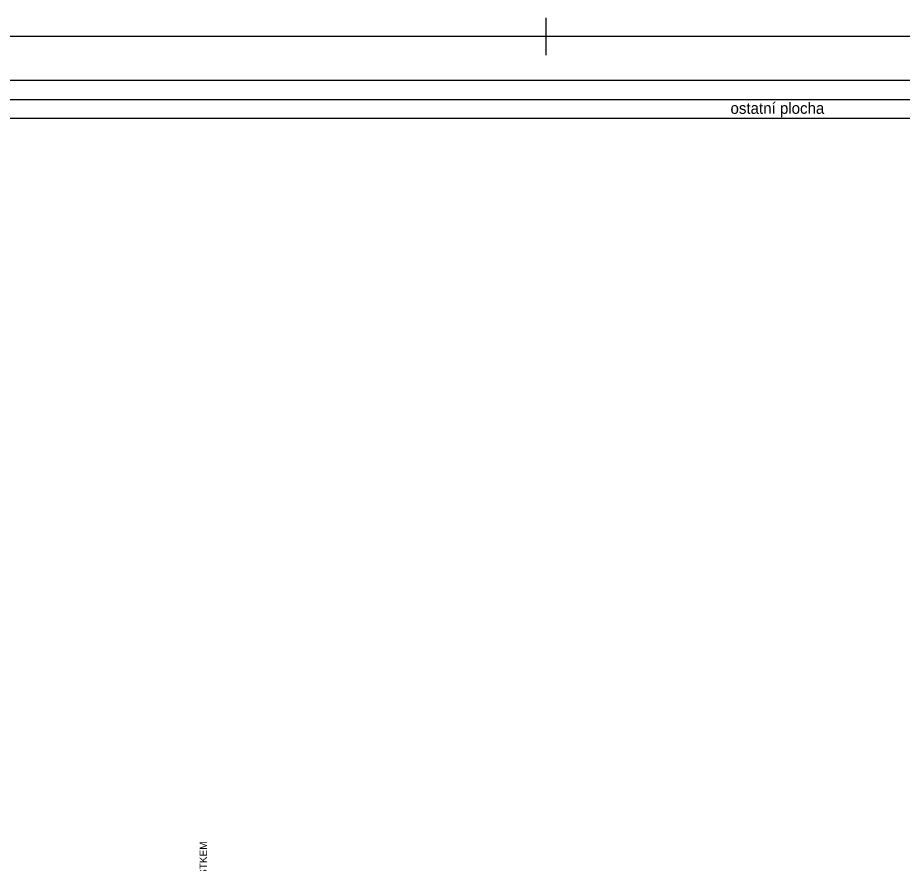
# Model space of a CAD drawing. Extents: x -24 to 1036, y -50 to 554.
# Drawn here: x 260.6 to 496.1, y 328.9 to 554 of the extents above; entities that cross this region are included whole.
import ezdxf

# ---------------------------------------------------------------- set-up
doc = ezdxf.new("R2010")
doc.units = 0
doc.layers.add('POPISY_NAD_TERENEM', color=7, linetype='Continuous')
doc.layers.add('TABULKY', color=7, linetype='Continuous')

msp = doc.modelspace()

# ---------------------------------------------------------------- linework, layer by layer
for p, q in [((401.15, 554.04), (401.15, 544.04)), ((401.15, 554.04), (401.15, 544.04)), ((401.15, 554.04), (401.15, 544.04)), ((401.15, 554.04), (401.15, 544.04)), ((401.15, 554.04), (401.15, 544.04)), ((401.15, 554.04), (401.15, 544.04)), ((401.15, 554.04), (401.15, 544.04)), ((401.15, 554.04), (401.15, 544.04)), ((401.15, 554.04), (401.15, 544.04)), ((401.15, 554.04), (401.15, 544.04)), ((401.15, 554.04), (401.15, 544.04)), ((401.15, 554.04), (401.15, 544.04)), ((401.15, 554.04), (401.15, 544.04)), ((401.15, 554.04), (401.15, 544.04)), ((401.15, 554.04), (401.15, 544.04)), ((401.15, 554.04), (401.15, 544.04)), ((401.15, 554.04), (401.15, 544.04)), ((401.15, 554.04), (401.15, 544.04)), ((401.15, 554.04), (401.15, 544.04)), ((401.15, 554.04), (401.15, 544.04)), ((406.15, 549.04), (396.15, 549.04)), ((406.15, 549.04), (396.15, 549.04)), ((406.15, 549.04), (396.15, 549.04)), ((406.15, 549.04), (396.15, 549.04)), ((406.15, 549.04), (396.15, 549.04)), ((406.15, 549.04), (396.15, 549.04)), ((406.15, 549.04), (396.15, 549.04)), ((406.15, 549.04), (396.15, 549.04)), ((406.15, 549.04), (396.15, 549.04)), ((406.15, 549.04), (396.15, 549.04)), ((406.15, 549.04), (396.15, 549.04)), ((406.15, 549.04), (396.15, 549.04)), ((406.15, 549.04), (396.15, 549.04)), ((406.15, 549.04), (396.15, 549.04)), ((406.15, 549.04), (396.15, 549.04)), ((406.15, 549.04), (396.15, 549.04)), ((406.15, 549.04), (396.15, 549.04)), ((406.15, 549.04), (396.15, 549.04)), ((406.15, 549.04), (396.15, 549.04)), ((406.15, 549.04), (396.15, 549.04))]:
    msp.add_line(p, q)
msp.add_lwpolyline([(1031.15, 549.04), (-19.35, 549.04), (-19.35, -44.96), (1031.15, -44.96)], close=True)
msp.add_lwpolyline([(1031.15, 549.04), (-19.35, 549.04), (-19.35, -44.96), (1031.15, -44.96)], close=True)
at = {"layer": 'TABULKY'}
for points in [[(70, 527.27), (859.4, 527.27), (859.4, 537.27), (70, 537.27), (70, 527.27)], [(70, 527.27), (859.4, 527.27), (859.4, 537.27), (70, 537.27), (70, 527.27)], [(70, 532.27), (859.4, 532.27)], [(70, 532.27), (859.4, 532.27)]]:
    msp.add_lwpolyline(points, dxfattribs=at)

# ---------------------------------------------------------------- texts
at = {"layer": 'POPISY_NAD_TERENEM'}
msp.add_text('PŘIPOJENÍ SJEZDU HS83 S PROPUSTKEM ', height=2, rotation=90, dxfattribs=at).set_placement((311, 280))
at = {"layer": 'TABULKY'}
msp.add_text('ostatní plocha', height=3, dxfattribs=at).set_placement((450.33, 528.44))

doc.saveas('drawing.dxf')
